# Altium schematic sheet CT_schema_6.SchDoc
size 367 x 245 mm
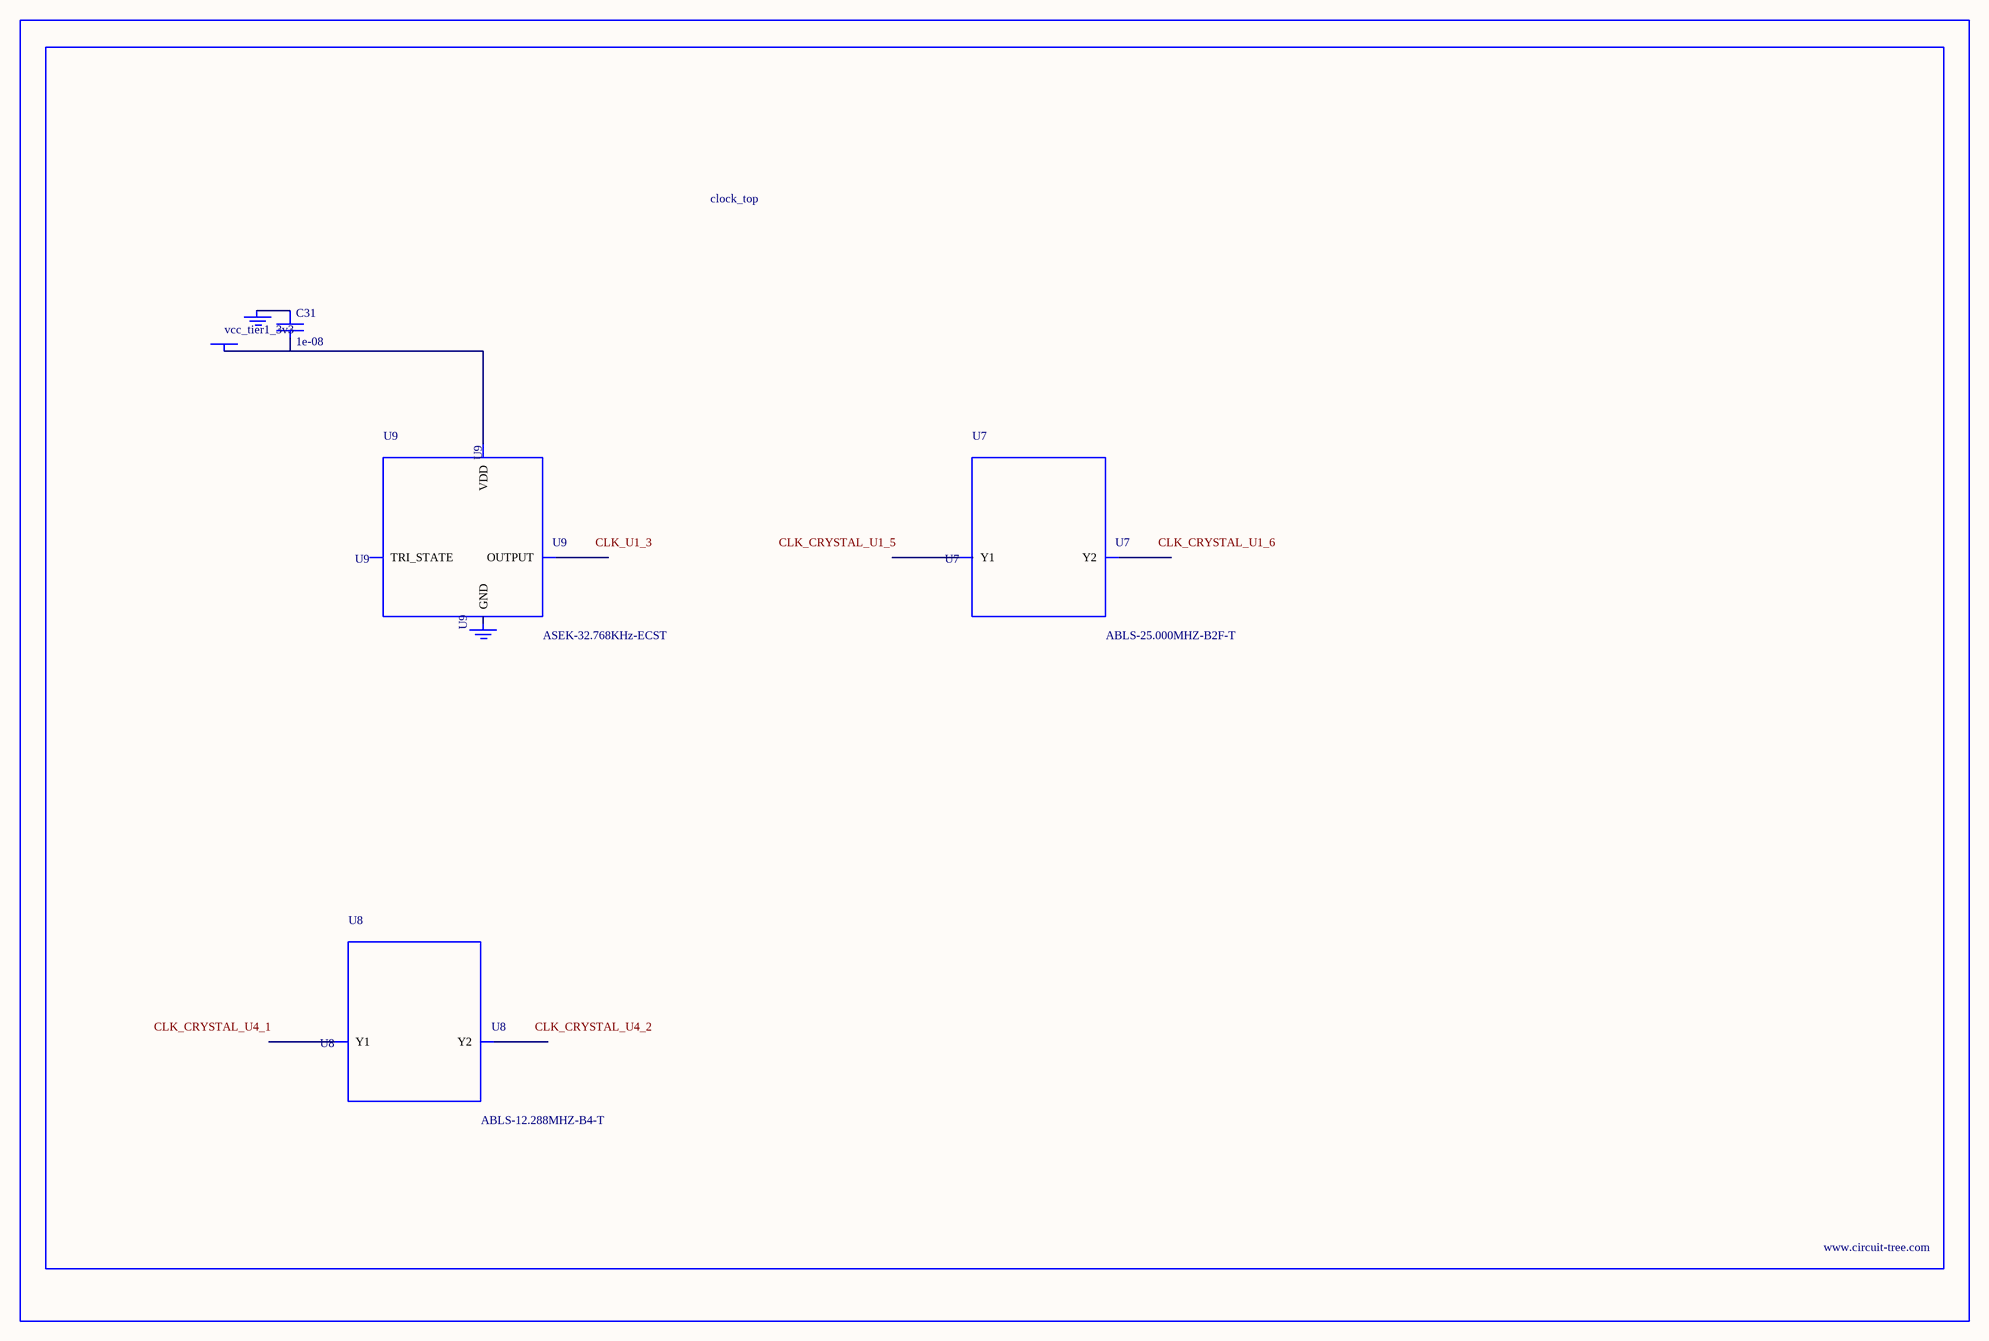
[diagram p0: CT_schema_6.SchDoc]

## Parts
BORDER5  (no value)
C31  1e-08  [C0402]
GND_INSTANCE_5_0  (no value)
GND_INSTANCE_5_1  (no value)
POWER_INSTANCE_5_0  vcc_tier1_3v3
U7  ABLS-25.000MHZ-B2F-T  [ABLS-25.000MHZ-B2F-T]
U8  ABLS-12.288MHZ-B4-T  [ABLS-12.288MHZ-B4-T]
U9  ASEK-32.768KHz-ECST  [ASEK]

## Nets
NetC31_1: C31.1 GND_INSTANCE_5_0.0(GND)
NetC31_2: C31.2 POWER_INSTANCE_5_0.0(PWR) U9.4(VDD)

Not connected (* = marked no-connect by the designer): GND_INSTANCE_5_1 0(GND); U7 1(Y1) 2(Y2); U8 1(Y1) 2(Y2); U9 1(TRI_STATE) 2(GND) 3(OUTPUT)

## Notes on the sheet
- Labels drawn without touching a wire or pin: CLK_CRYSTAL_U1_5, CLK_CRYSTAL_U1_6, CLK_CRYSTAL_U4_1, CLK_CRYSTAL_U4_2, CLK_U1_3

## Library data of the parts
BORDER5 = BORDER_PAGE5
C31 = C0402C103K3RAC
GND_INSTANCE_5_0 GND_INSTANCE_5_1 = GND
POWER_INSTANCE_5_0 = PWR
